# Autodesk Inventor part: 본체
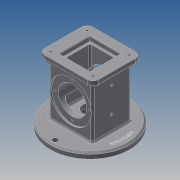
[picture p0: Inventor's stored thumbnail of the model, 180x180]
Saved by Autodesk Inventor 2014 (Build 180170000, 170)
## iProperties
Created: 2019-08
Part Number: 본체
Material: Generic
Document SubType Name: Modeling
Designer: kb542-17
Density: 1 g/cm^3
Appearance: Default
Mass: 384.755 g
Surface Area: 783.577 cm^2
Volume: 384.755 cm^3
Author: kb542-17
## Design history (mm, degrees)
sketch "스케치1"
  geometry: L1 (-37, 33)-(37, 33); L2 (37, 33)-(37, -33); L3 (37, -33)-(-37, -33); L4 (-37, -33)-(-37, 33); L5 (-37, 33)-(37, -33); L6 (37, 33)-(-37, -33); 1 further point
  constraints: 12 end point, 2 midpoint, 2 parallel, 1 horizontal, 1 perpendicular
  dimensions: "d0" = 66 distance of L1.end L2.end; "d1" = 74 distance of L1.start L1.end
extrude "돌출1" new body sketch "스케치1" stored distance "d2" = 88; taper "d3" = 0 deg
sketch "스케치2"
  geometry: L1 (-46, 41)-(46, 41); L2 (46, 41)-(46, -41); L3 (46, -41)-(-46, -41); L4 (-46, -41)-(-46, 41); L5 (-46, 41)-(46, -41); L6 (46, 41)-(-46, -41); 1 further point
  constraints: 12 end point, 2 midpoint, 2 parallel, 1 horizontal, 1 perpendicular
  dimensions: "d4" = 82 distance of L1.end L2.end; "d5" = 92 distance of L1.start L1.end
extrude "돌출2" join sketch "스케치2" distance "d6" = 10; taper "d7" = 0 deg
sketch "스케치3"
  geometry: C1 r 67.5 at (0, 0); 1 further point
  constraints: 1 centre point, 1 coincident
  dimensions: "d8" = 135 diameter of C1
extrude "돌출3" join sketch "스케치3" distance "d9" = 10; taper "d10" = 0 deg
sketch "스케치4"
  geometry: L1 (-33, 44)-(-33, -44) reference; L2 (33, -44)-(33, 44) reference; L3 (-33, 0)-(33, 0); L4 (-33, 35)-(-30, 35); L5 (-30, 35)-(-30, 24); L6 (-30, 24)-(30, 24); L7 (30, 24)-(30, 35); L8 (30, 35)-(33, 35); 2 further points
  constraints: 12 end point, 3 midpoint, 3 parallel, 2 point on line, 1 coincident, 1 collinear, 1 perpendicular
  dimensions: "d11" = 3 distance between parallel lines of L1 L5; "d12" = 3 distance between parallel lines of L2 L7; "d13" = 70 diameter of L4 L3; "d14" = 48 diameter of L6 L3; "d15" = 70 diameter of L8 L3
revolve "회전1" sketch "스케치4" stored, may be unused: angle "d16" = 90 deg
sketch "스케치5"
  geometry: C1 r 67.5 at (0, 0) reference; C2 r 25 at (0, 0)
  constraints: 1 centre point, 1 coincident
  dimensions: "d17" = 50 diameter of C2
extrude "돌출4" cut sketch "스케치5" distance "d18" = 18; taper "d19" = 0 deg
sketch "스케치6"
  geometry: L1 (-26, 26)-(26, 26); L2 (26, 26)-(26, -26); L3 (26, -26)-(-26, -26); L4 (-26, -26)-(-26, 26); L5 (-26, 26)-(26, -26); L6 (26, 26)-(-26, -26); 1 further point
  constraints: 12 end point, 2 midpoint, 2 parallel, 1 horizontal, 1 perpendicular
  dimensions: "d20" = 52 distance of L1.end L2.end; "d21" = 52 distance of L1.start L1.end
extrude "돌출5" cut sketch "스케치6" distance "d22" = 8; taper "d23" = 0 deg
sketch "스케치7"
  geometry: L1 (-22, 22)-(22, 22); L2 (22, 22)-(22, -22); L3 (22, -22)-(-22, -22); L4 (-22, -22)-(-22, 22); L5 (-22, 22)-(22, -22); L6 (22, 22)-(-22, -22); 1 further point
  constraints: 12 end point, 2 midpoint, 2 parallel, 1 horizontal, 1 perpendicular
  dimensions: "d24" = 44 distance of L1.start L1.end; "d25" = 44 distance of L1.end L2.end
extrude "돌출6" cut sketch "스케치7" distance "d26" = 74; taper "d27" = 0 deg
sketch "스케치8"
  geometry: C1 r 25 at (0, 0) reference; C2 r 12.5 at (0, 0)
  constraints: 1 centre point, 1 coincident
  dimensions: "d28" = 25 diameter of C2
extrude "돌출7" cut sketch "스케치8" stored distance "d29" = 74; taper "d30" = 0 deg
sketch "스케치9"
  geometry: C1 r 24 at (0, 0) reference; 1 further point
  constraints: 1 vertical alignment
  dimensions: "d31" = 29 distance of C1.centre point (0, 29)
hole "구멍1" sketch "스케치9" at (0, 29) diameter "d32" = 3.242; stored, may be unused: countersink angle "d36" = 90 deg, drill point angle "d38" = 118 deg; dims "d33" = 4, "d34" = 4, "d35" = 2, "d37" = 6
sketch "스케치10"
  geometry: C1 r 35 at (0, 0) reference; 1 further point
  constraints: 1 vertical alignment
  dimensions: "d42" = 29 distance of C1.centre point (0, -29)
hole "구멍2" sketch "스케치10" at (0, -29) diameter "d43" = 3.242; stored, may be unused: countersink angle "d47" = 90 deg, drill point angle "d49" = 118 deg; dims "d44" = 4, "d45" = 4, "d46" = 2, "d48" = 6
fillet "모깎기1" dims "d53" = 10
chamfer "모따기1" distance "d61" = 3; stored, may be unused: second distance "d62" = 2, angle "d63" = 45 deg
sketch "스케치13"
  geometry: C1 r 64.5 at (0, 0) reference; 1 further point
  constraints: 1 vertical alignment
  dimensions: "d64" = 59 distance of point (0, 59) C1.centre
hole "구멍4" sketch "스케치13" at (0, 59) diameter "d65" = 9; stored, may be unused: countersink angle "d69" = 90 deg, drill point angle "d71" = 118 deg; dims "d66" = 4, "d67" = 4, "d68" = 2, "d70" = 6
sketch "스케치14"
  geometry: L1 (98, -34.5)-(98, 100.5) reference; 3 further points
  constraints: 2 horizontal alignment
  dimensions: "d75" = 37 distance from line of L1 point (61, 33); "d76" = 43 distance of point (61, 33) point (18, 33)
sketch "스케치15"
  geometry: C1 r 64.5 at (0, 0) reference; C2 r 59 at (0, 0)
  constraints: 1 centre point, 1 coincident, 1 other
  dimensions: "d91" = 118 diameter of C2
feature "엠보싱1" sketch "스케치15" dims "d9" = 10, "d10" = 0, "d92" = 0.5, "d93" = 0
fillet "모깎기2" dims "d94" = 3
fillet "모깎기3" dims "d95" = 3
fillet "모깎기4" dims "d96" = 3
chamfer "모따기2" distance "d97" = 1; stored, may be unused: second distance "d98" = 2, angle "d99" = 45 deg
fillet "모깎기5" dims "d100" = 3
fillet "모깎기6" dims "d101" = 3
fillet "모깎기7" dims "d102" = 3
fillet "모깎기8" dims "d103" = 3
sketch "스케치16"
  geometry: A1 r 10 centre (-36, 31) between (-36, 41) and (-46, 31) reference; 5 further points
  constraints: 1 coincident, 1 horizontal alignment, 1 vertical alignment
  dimensions: "d104" = 62 distance of point (-36, -31) point (-36, 31); "d105" = 72 distance of point (36, 31) point (-36, 31); "d106" = 62 distance of point (36, 31) point (36, -31); "d107" = 72 distance of point (-36, -31) point (36, -31)
hole "구멍7" sketch "스케치16" at (-36, 31), (-36, -31), (36, -31), (36, 31) diameter "d108" = 3.242; stored, may be unused: countersink angle "d112" = 90 deg, drill point angle "d114" = 118 deg; dims "d109" = 4, "d110" = 4, "d111" = 2, "d113" = 6
hole "구멍9" sketch "스케치14" diameter "d128" = 4.92; stored, may be unused: countersink angle "d132" = 82 deg, drill point angle "d134" = 118 deg; dims "d129" = 4, "d130" = 3.023, "d131" = 2, "d133" = 6
sketch "스케치17"
  geometry: L1 (95, -37.5)-(95, 97.5) reference; 2 further points
  constraints: 1 horizontal alignment
  dimensions: "d135" = 37 distance from line of L1 point (58, 30)
hole "구멍10" sketch "스케치17" at (58, 30) diameter "d136" = 4.92; stored, may be unused: countersink angle "d140" = 82 deg, drill point angle "d142" = 118 deg; dims "d137" = 4, "d138" = 3.023, "d139" = 2, "d141" = 6
feature "스레드4" dims "d143" = 10, "d144" = 0
feature "스레드5" dims "d145" = 10, "d146" = 0
node "솔리드1"
pattern_circular "원형 패턴1" dims angle "d40" = 360 deg
pattern_circular "원형 패턴2" dims angle "d51" = 360 deg
pattern_circular "원형 패턴3" dims angle "d73" = 180 deg
